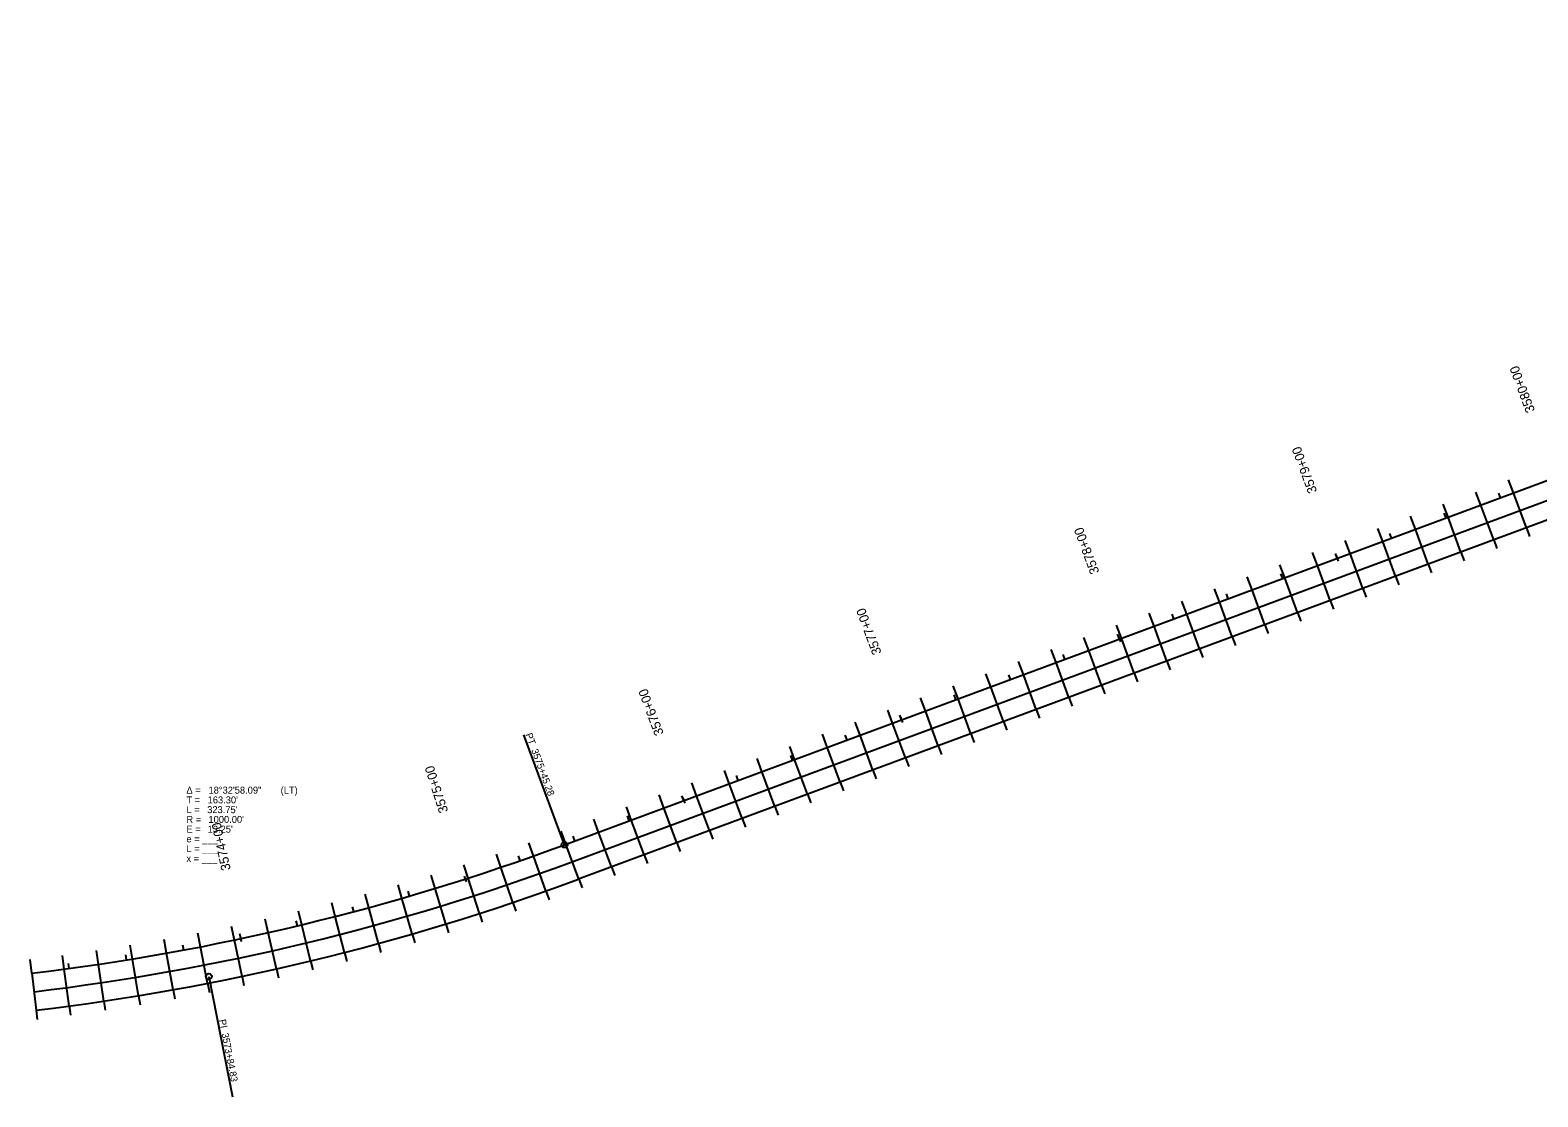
# Model space of a CAD drawing. Extents: x 19570301 to 19572259, y 7727180 to 7727858.
# Drawn here: x 19570959 to 19571608, y 7727204 to 7727663 of the extents above; entities that cross this region are included whole.
import ezdxf

# ---------------------------------------------------------------- set-up
doc = ezdxf.new("R2010")
doc.units = 0
for name, color, linetype in [('Alignment', 7, 'Continuous'), ('NamedBoundary', 7, 'Continuous'), ('SheetText', 7, 'Continuous'), ('Terrain', 7, 'Continuous')]:
    doc.layers.add(name, color=color, linetype=linetype)

msp = doc.modelspace()

# ---------------------------------------------------------------- linework, layer by layer
at = {"layer": 'Alignment'}
for p, q in [((19571189.23, 7727312.65), (19571171.7, 7727359.91)), ((19571171.7, 7727359.91), (19571171.7, 7727359.91)), ((19571036.12, 7727255.87), (19571046.26, 7727204.05)), ((19571046.26, 7727204.05), (19571046.26, 7727204.05))]:
    msp.add_line(p, q, dxfattribs=at)
for centre in [(19571189.23, 7727312.65), (19571036.12, 7727255.87)]:
    msp.add_circle(centre, 1.25, dxfattribs=at)
at = {"layer": 'NamedBoundary'}
for p, q in [((19571189.23, 7727312.65), (19572135.22, 7727663.5)), ((19571192.01, 7727305.15), (19572134.9, 7727654.85)), ((19572135.09, 7727646.38), (19571194.79, 7727297.65)), ((19571597.69, 7727464.14), (19571595.6, 7727469.77)), ((19571583.62, 7727458.93), (19571581.54, 7727464.55)), ((19571603.25, 7727449.14), (19571597.69, 7727464.14)), ((19571569.56, 7727453.71), (19571567.47, 7727459.33)), ((19571589.19, 7727443.92), (19571583.62, 7727458.93)), ((19571541.43, 7727443.28), (19571539.35, 7727448.9)), ((19571555.5, 7727448.49), (19571553.41, 7727454.12)), ((19571561.06, 7727433.49), (19571555.5, 7727448.49)), ((19571575.12, 7727438.71), (19571569.56, 7727453.71)), ((19571603.25, 7727449.14), (19571604.64, 7727445.39)), ((19571527.37, 7727438.06), (19571525.28, 7727443.69)), ((19571547, 7727428.28), (19571541.43, 7727443.28)), ((19571589.19, 7727443.92), (19571590.58, 7727440.17)), ((19571513.3, 7727432.85), (19571511.22, 7727438.47)), ((19571532.93, 7727423.06), (19571527.37, 7727438.06)), ((19571575.12, 7727438.71), (19571576.51, 7727434.96)), ((19571499.24, 7727427.63), (19571497.15, 7727433.26)), ((19571518.87, 7727417.84), (19571513.3, 7727432.85)), ((19571561.06, 7727433.49), (19571562.45, 7727429.74)), ((19571471.11, 7727417.2), (19571469.03, 7727422.82)), ((19571485.18, 7727422.41), (19571483.09, 7727428.04)), ((19571490.74, 7727407.41), (19571485.18, 7727422.41)), ((19571504.8, 7727412.63), (19571499.24, 7727427.63)), ((19571532.93, 7727423.06), (19571534.32, 7727419.31)), ((19571547, 7727428.28), (19571548.39, 7727424.53)), ((19571457.05, 7727411.98), (19571454.96, 7727417.61)), ((19571476.68, 7727402.2), (19571471.11, 7727417.2)), ((19571518.87, 7727417.84), (19571520.26, 7727414.09)), ((19571442.98, 7727406.77), (19571440.9, 7727412.39)), ((19571462.61, 7727396.98), (19571457.05, 7727411.98)), ((19571504.8, 7727412.63), (19571506.19, 7727408.88)), ((19571428.92, 7727401.55), (19571426.83, 7727407.18)), ((19571448.55, 7727391.76), (19571442.98, 7727406.77)), ((19571490.74, 7727407.41), (19571492.13, 7727403.66)), ((19571400.79, 7727391.12), (19571398.71, 7727396.74)), ((19571414.86, 7727396.33), (19571412.77, 7727401.96)), ((19571420.42, 7727381.33), (19571414.86, 7727396.33)), ((19571434.48, 7727386.55), (19571428.92, 7727401.55)), ((19571462.61, 7727396.98), (19571464, 7727393.23)), ((19571476.68, 7727402.2), (19571478.07, 7727398.45)), ((19571386.73, 7727385.9), (19571384.64, 7727391.53)), ((19571406.36, 7727376.12), (19571400.79, 7727391.12)), ((19571448.55, 7727391.76), (19571449.94, 7727388.01)), ((19571372.66, 7727380.69), (19571370.58, 7727386.31)), ((19571392.29, 7727370.9), (19571386.73, 7727385.9)), ((19571434.48, 7727386.55), (19571435.87, 7727382.8)), ((19571358.6, 7727375.47), (19571356.51, 7727381.1)), ((19571378.23, 7727365.68), (19571372.66, 7727380.69)), ((19571420.42, 7727381.33), (19571421.81, 7727377.58)), ((19571330.47, 7727365.04), (19571328.39, 7727370.66)), ((19571344.54, 7727370.25), (19571342.45, 7727375.88)), ((19571350.1, 7727355.25), (19571344.54, 7727370.25)), ((19571364.16, 7727360.47), (19571358.6, 7727375.47)), ((19571392.29, 7727370.9), (19571393.68, 7727367.15)), ((19571406.36, 7727376.12), (19571407.75, 7727372.37)), ((19571316.41, 7727359.82), (19571314.32, 7727365.45)), ((19571336.04, 7727350.04), (19571330.47, 7727365.04)), ((19571378.23, 7727365.68), (19571379.62, 7727361.93)), ((19571302.34, 7727354.61), (19571300.26, 7727360.23)), ((19571321.97, 7727344.82), (19571316.41, 7727359.82)), ((19571364.16, 7727360.47), (19571365.56, 7727356.72)), ((19571288.28, 7727349.39), (19571286.19, 7727355.02)), ((19571307.91, 7727339.6), (19571302.34, 7727354.61)), ((19571350.1, 7727355.25), (19571351.49, 7727351.5)), ((19571260.15, 7727338.96), (19571258.07, 7727344.58)), ((19571274.22, 7727344.17), (19571272.13, 7727349.8)), ((19571279.78, 7727329.17), (19571274.22, 7727344.17)), ((19571293.84, 7727334.39), (19571288.28, 7727349.39)), ((19571321.97, 7727344.82), (19571323.36, 7727341.07)), ((19571336.04, 7727350.04), (19571337.43, 7727346.29)), ((19571246.09, 7727333.74), (19571244, 7727339.37)), ((19571265.72, 7727323.96), (19571260.15, 7727338.96)), ((19571307.91, 7727339.6), (19571309.3, 7727335.85)), ((19571232.03, 7727328.53), (19571229.94, 7727334.15)), ((19571251.65, 7727318.74), (19571246.09, 7727333.74)), ((19571293.84, 7727334.39), (19571295.24, 7727330.64)), ((19571217.96, 7727323.31), (19571215.87, 7727328.94)), ((19571237.59, 7727313.53), (19571232.03, 7727328.53)), ((19571279.78, 7727329.17), (19571281.17, 7727325.42)), ((19571189.83, 7727312.88), (19571187.74, 7727318.5)), ((19571203.9, 7727318.09), (19571201.81, 7727323.72)), ((19571223.52, 7727308.31), (19571217.96, 7727323.31)), ((19571251.65, 7727318.74), (19571253.04, 7727314.99)), ((19571265.72, 7727323.96), (19571267.11, 7727320.21)), ((19571175.85, 7727307.8), (19571173.84, 7727313.46)), ((19571195.4, 7727297.88), (19571189.83, 7727312.88)), ((19571209.46, 7727303.09), (19571203.9, 7727318.09)), ((19571237.59, 7727313.53), (19571238.98, 7727309.77)), ((19571161.8, 7727302.93), (19571159.88, 7727308.62)), ((19571181.2, 7727292.72), (19571175.85, 7727307.8)), ((19571223.52, 7727308.31), (19571224.92, 7727304.56)), ((19571133.49, 7727293.83), (19571131.74, 7727299.57)), ((19571147.68, 7727298.28), (19571145.84, 7727303.99)), ((19571166.92, 7727287.78), (19571161.8, 7727302.93)), ((19571209.46, 7727303.09), (19571210.85, 7727299.34)), ((19571119.23, 7727289.59), (19571117.57, 7727295.36)), ((19571138.16, 7727278.52), (19571133.49, 7727293.83)), ((19571152.58, 7727283.04), (19571147.68, 7727298.28)), ((19571181.2, 7727292.72), (19571182.54, 7727288.95)), ((19571195.4, 7727297.88), (19571196.79, 7727294.13)), ((19571090.54, 7727281.76), (19571089.05, 7727287.57)), ((19571104.92, 7727285.57), (19571103.34, 7727291.36)), ((19571123.68, 7727274.22), (19571119.23, 7727289.59)), ((19571166.92, 7727287.78), (19571168.21, 7727283.99)), ((19571061.63, 7727274.78), (19571060.31, 7727280.63)), ((19571076.11, 7727278.16), (19571074.71, 7727283.99)), ((19571094.53, 7727266.26), (19571090.54, 7727281.76)), ((19571109.13, 7727270.13), (19571104.92, 7727285.57)), ((19571152.58, 7727283.04), (19571153.8, 7727279.24)), ((19571032.53, 7727268.67), (19571031.38, 7727274.55)), ((19571047.1, 7727271.61), (19571045.87, 7727277.49)), ((19571065.16, 7727259.17), (19571061.63, 7727274.78)), ((19571079.87, 7727262.61), (19571076.11, 7727278.16)), ((19571123.68, 7727274.22), (19571124.79, 7727270.38)), ((19571138.16, 7727278.52), (19571139.33, 7727274.7)), ((19570988.56, 7727261.12), (19570987.68, 7727267.06)), ((19571003.25, 7727263.42), (19571002.28, 7727269.34)), ((19571017.91, 7727265.93), (19571016.85, 7727271.84)), ((19571035.58, 7727252.96), (19571032.53, 7727268.67)), ((19571050.39, 7727255.96), (19571047.1, 7727271.61)), ((19571109.13, 7727270.13), (19571110.19, 7727266.27)), ((19570959.89, 7727257.28), (19570959.18, 7727263.24)), ((19570973.84, 7727259.04), (19570973.04, 7727264.99)), ((19570990.92, 7727245.3), (19570988.56, 7727261.12)), ((19571005.84, 7727247.63), (19571003.25, 7727263.42)), ((19571020.73, 7727250.18), (19571017.91, 7727265.93)), ((19571079.87, 7727262.61), (19571080.81, 7727258.72)), ((19571094.53, 7727266.26), (19571095.52, 7727262.39)), ((19570959.89, 7727257.28), (19570961.78, 7727241.39)), ((19570975.95, 7727243.19), (19570973.84, 7727259.04)), ((19571050.39, 7727255.96), (19571051.22, 7727252.04)), ((19571065.16, 7727259.17), (19571066.04, 7727255.27)), ((19571005.84, 7727247.63), (19571006.49, 7727243.68)), ((19571020.73, 7727250.18), (19571021.44, 7727246.25)), ((19571035.58, 7727252.96), (19571036.35, 7727249.03)), ((19570961.78, 7727241.39), (19570962.26, 7727237.42)), ((19570975.95, 7727243.19), (19570976.48, 7727239.22)), ((19570990.92, 7727245.3), (19570991.5, 7727241.34))]:
    msp.add_line(p, q, dxfattribs=at)
for radius in [1000, 1008, 1016]:
    msp.add_arc((19570841.5, 7728250.25), radius, 276.79924, 290.34846, dxfattribs=at)
at = {"layer": 'SheetText'}
for p, q in [((19571521.81, 7727436), (19571521.05, 7727438.05)), ((19571428.05, 7727401.23), (19571427.29, 7727403.28)), ((19571334.29, 7727366.46), (19571333.53, 7727368.5)), ((19571240.53, 7727331.68), (19571239.77, 7727333.73)), ((19571146.06, 7727299.04), (19571146.81, 7727296.71)), ((19571049.83, 7727272.19), (19571049.37, 7727274.33))]:
    msp.add_line(p, q, dxfattribs=at)
at = {"layer": 'Terrain'}
for p, q in [((19571592.13, 7727462.08), (19571591.37, 7727464.13)), ((19571568.69, 7727453.39), (19571567.93, 7727455.43)), ((19571545.25, 7727444.69), (19571544.49, 7727446.74)), ((19571521.39, 7727437.15), (19571522.24, 7727434.85)), ((19571498.37, 7727427.31), (19571497.61, 7727429.36)), ((19571474.93, 7727418.61), (19571474.17, 7727420.66)), ((19571451.49, 7727409.92), (19571450.73, 7727411.97)), ((19571427.63, 7727402.38), (19571428.48, 7727400.08)), ((19571404.61, 7727392.53), (19571403.85, 7727394.58)), ((19571381.17, 7727383.84), (19571380.41, 7727385.89)), ((19571357.73, 7727375.15), (19571356.97, 7727377.2)), ((19571333.87, 7727367.6), (19571334.72, 7727365.31)), ((19571310.85, 7727357.76), (19571310.09, 7727359.81)), ((19571287.41, 7727349.07), (19571286.65, 7727351.12)), ((19571263.97, 7727340.38), (19571263.21, 7727342.42)), ((19571240.11, 7727332.83), (19571240.96, 7727330.53)), ((19571217.09, 7727322.99), (19571216.33, 7727325.04)), ((19571193.65, 7727314.3), (19571192.89, 7727316.34)), ((19571170.14, 7727305.8), (19571169.43, 7727307.86)), ((19571146.06, 7727299.04), (19571146.81, 7727296.71)), ((19571122.53, 7727290.55), (19571121.92, 7727292.65)), ((19571098.45, 7727283.83), (19571097.89, 7727285.94)), ((19571074.21, 7727277.7), (19571073.71, 7727279.83)), ((19571049.57, 7727273.39), (19571050.08, 7727270.99)), ((19571025.32, 7727267.29), (19571024.91, 7727269.44)), ((19570975.96, 7727259.33), (19570975.67, 7727261.49)), ((19571000.69, 7727263), (19571000.34, 7727265.16))]:
    msp.add_line(p, q, dxfattribs=at)

# ---------------------------------------------------------------- texts
at = {"layer": 'Alignment'}
for s, rotation, p in [('PT', 290.34846, (19571172.32, 7727360.14)), ('3575+45.28', 290.34846, (19571174.84, 7727353.33)), ('PI ', 281.07373, (19571040.45, 7727237.13)), ('3573+84.83', 281.07373, (19571041.6, 7727231.26))]:
    msp.add_text(s, height=3, rotation=rotation, dxfattribs=at).set_placement(p)
for s, p in [('18°32\'58.09"', (19571035.95, 7727334.65)), (' (LT)', (19571065.89, 7727334.65)), ('T = ', (19571026.45, 7727330.45)), ('Δ = ', (19571026.45, 7727334.65)), ("163.30'", (19571035.57, 7727330.45)), ('L = ', (19571026.45, 7727326.25)), ('R = ', (19571026.45, 7727322.05)), ("323.75'", (19571035.39, 7727326.25)), ("1000.00'", (19571035.93, 7727322.05)), ('E = ', (19571026.45, 7727317.85)), ("13.25'", (19571035.58, 7727317.85)), ('e = ___ ', (19571026.45, 7727313.65)), ('L = ___', (19571026.45, 7727309.45)), ('x = ___', (19571026.45, 7727305.25))]:
    msp.add_text(s, height=3, dxfattribs=at).set_placement(p)
at = {"layer": 'SheetText'}
for s, rotation, p in [('3580+00', 110.34846, (19571607.02, 7727499.6)), ('3575+00', 107.75415, (19571139.19, 7727327.06))]:
    msp.add_text(s, height=4.008, rotation=rotation, dxfattribs=at).set_placement(p)
at = {"layer": 'Terrain'}
for s, rotation, p in [('3580+00', 110.34846, (19571607.02, 7727499.6)), ('3579+00', 110.34846, (19571513.26, 7727464.83)), ('3578+00', 110.34846, (19571419.5, 7727430.05)), ('3577+00', 110.34846, (19571325.74, 7727395.28)), ('3576+00', 110.34846, (19571231.98, 7727360.51)), ('3575+00', 107.75415, (19571139.19, 7727327.06)), ('3574+00', 102.02457, (19571045.54, 7727301.95))]:
    msp.add_text(s, height=4.008, rotation=rotation, dxfattribs=at).set_placement(p)

doc.saveas('drawing.dxf')
